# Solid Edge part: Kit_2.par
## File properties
Sűrűség: 0,000 kg/m^3
Pontosság: 0,990
Author: ahadarics
Last saved by: ahadarics
Revision: 76
Username: ahadarics
Dokumentum tartalom típus: 0
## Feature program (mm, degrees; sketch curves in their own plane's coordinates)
base feature "unnamed BaseFeature 1"
sketch for "Furat_1" plane through (0, 14.75, 17.5) normal (0, 0, 1) x-axis (0, 1, 0)
  hole centre (2, 0) bore radius 4.283
hole "Furat_1" nominal diameter 9.728 finite  ThreadDepth = 9 mm
chamfer "Letörés_1" setback 1
thread "unnamed Thread 1"
sketch for "Furat_2" plane through (17.5, 16.75, 0) normal (1, 0, 0) x-axis (0, 1, 0)
  hole centre (0, 0) bore radius 3.4585
hole "Furat_2" nominal diameter 8 finite  ThreadDepth = 6.5 mm
sketch for "Furat_3" plane through (-17.5, 16.75, 0) normal (-1, 0, 0) x-axis (0, -1, 0)
  hole centre (0, 0) bore radius 3.4585
hole "Furat_3" nominal diameter 8 finite  ThreadDepth = 6.5 mm
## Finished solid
Body 1: solid body, 35 faces, 38 edges, 4 vertices.
  Faces by surface: cylinder 16, plane 15, cone 4
  Edges by curve: circle 31, line 4, intersection 3
Bounding box of the edges (mm): 38.000 x 38.000 x 36.500, from (-19, 1.75, -19) to (19, 39.75, 17.5).
Cylindrical faces by radius (mm): R1.5 x1, R3.455 x2, R3.4585 x2, R4 x1, R4.28 x1, R4.283 x1, R5 x2, R14 x2, R15 x2, R16.8 x1, R19 x1
Conical faces (half-angle, radius in mm at the cone's reference point): 45 deg R5.283 x1, 45 deg R13.75 x1, 59 deg R2 x1, 59 deg R2.1415 x1
Planar faces by outward normal: +x 3, +y 4, +z 2, -x 3, -y 3
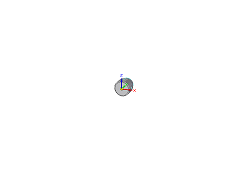
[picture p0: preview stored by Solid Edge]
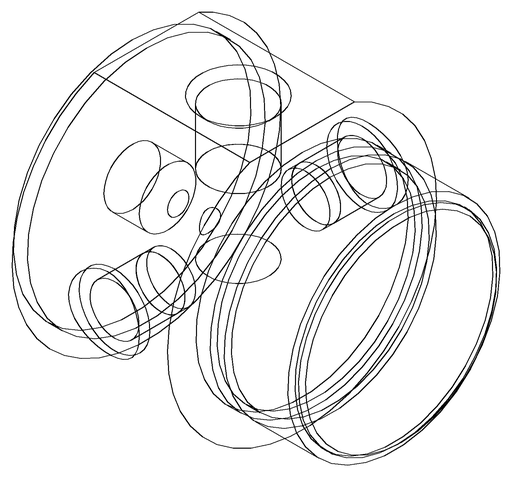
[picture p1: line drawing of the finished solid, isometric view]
